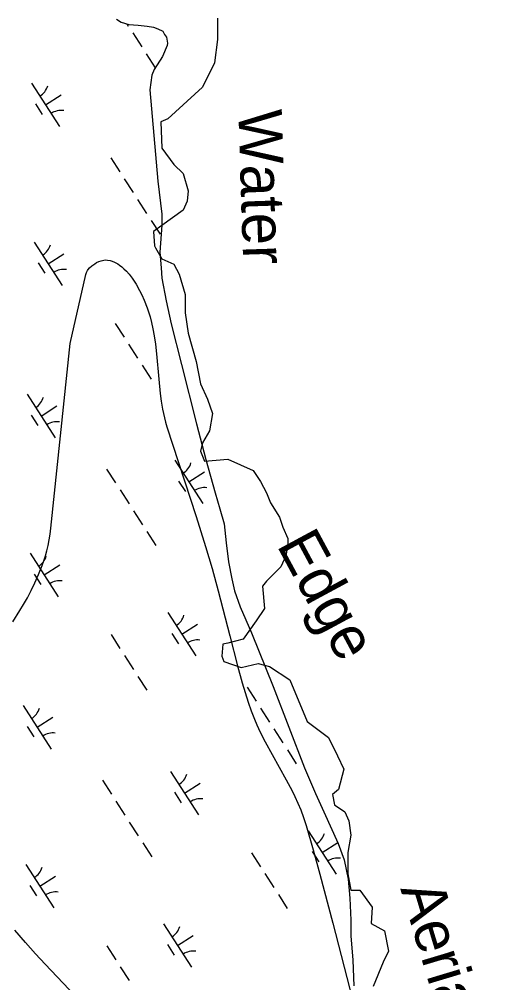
# Model space of a CAD drawing. Extents: x 3937982 to 3958556, y 219448 to 241894.
# Drawn here: x 3947936 to 3948387, y 229125 to 230057 of the extents above; entities that cross this region are included whole.
import ezdxf

# ---------------------------------------------------------------- set-up
doc = ezdxf.new("R2010")
doc.units = 0
for name, color, linetype in [('V-RIVR-EDGE', 7, 'Continuous'), ('V-RIVR-IDEN', 7, 'Continuous'), ('V-SITE-VEGE', 7, 'Continuous'), ('V-WETL-SWMP', 7, 'Continuous')]:
    doc.layers.add(name, color=color, linetype=linetype)

msp = doc.modelspace()

# ---------------------------------------------------------------- linework, layer by layer
at = {"layer": 'V-RIVR-EDGE'}
msp.add_lwpolyline([(3948127.892, 230057.732), (3948127.892, 230037.092), (3948124.944, 230014.485), (3948113.149, 229990.895), (3948079.73, 229960.426), (3948072.85, 229957.477), (3948073.833, 229931.922), (3948085.628, 229916.195), (3948094.474, 229907.349), (3948099.388, 229890.64), (3948098.405, 229880.811), (3948094.474, 229871.965), (3948073.833, 229857.222), (3948065.97, 229851.324), (3948066.953, 229837.564), (3948067.936, 229835.598), (3948073.833, 229824.786), (3948085.628, 229819.872), (3948090.542, 229810.043), (3948096.44, 229790.385), (3948096.44, 229772.693), (3948099.388, 229753.035), (3948107.251, 229725.514), (3948111.183, 229703.89), (3948118.063, 229689.146), (3948122.978, 229675.386), (3948120.029, 229658.677), (3948113.149, 229646.882), (3948111.183, 229639.019), (3948115.115, 229629.19), (3948137.721, 229631.156), (3948162.294, 229620.344), (3948169.174, 229609.532), (3948175.071, 229598.72), (3948179.003, 229588.891), (3948187.849, 229575.13), (3948190.798, 229565.302), (3948195.712, 229554.49), (3948195.712, 229548.592), (3948193.746, 229537.78), (3948188.832, 229526.969), (3948175.071, 229513.208), (3948171.14, 229508.294), (3948173.105, 229486.67), (3948165.242, 229474.875), (3948152.465, 229457.183), (3948137.721, 229453.251), (3948132.807, 229452.268), (3948131.824, 229440.474), (3948133.79, 229435.559), (3948150.499, 229429.662), (3948167.208, 229433.593), (3948178.02, 229430.645), (3948197.678, 229417.867), (3948214.387, 229377.568), (3948235.028, 229361.842), (3948243.874, 229344.15), (3948249.771, 229331.372), (3948244.857, 229311.714), (3948238.959, 229306.8), (3948240.925, 229296.971), (3948250.754, 229290.091), (3948254.686, 229281.245), (3948256.652, 229267.484), (3948253.703, 229250.775), (3948253.703, 229230.134), (3948256.652, 229214.408), (3948265.498, 229214.408), (3948277.292, 229197.698), (3948276.309, 229181.972), (3948289.087, 229175.092), (3948293.019, 229155.434), (3948288.104, 229144.622), (3948278.275, 229121.033)], dxfattribs=at)
at = {"layer": 'V-SITE-VEGE'}
for points in [[(3947951.202, 229511.544), (3947954.778, 229519.604), (3947958.182, 229528.323), (3947959.758, 229532.871), (3947961.247, 229537.602), (3947962.636, 229542.528), (3947963.895, 229547.654), (3947965.008, 229552.991), (3947965.945, 229558.559), (3947966.677, 229564.361), (3947985.369, 229743.168), (3948000.321, 229809.784), (3948000.96, 229811.727), (3948001.951, 229813.583), (3948002.785, 229814.764), (3948004.073, 229816.257), (3948006.058, 229818.092), (3948009.031, 229820.21), (3948010.829, 229821.232), (3948012.91, 229822.215), (3948015.251, 229823.069), (3948017.776, 229823.667), (3948019.013, 229823.806), (3948021.493, 229823.741), (3948024.057, 229823.247), (3948025.802, 229822.7), (3948028.147, 229821.715), (3948031.281, 229819.985), (3948033.056, 229818.801), (3948035.059, 229817.289), (3948037.296, 229815.372), (3948039.757, 229812.962), (3948042.414, 229809.964), (3948045.183, 229806.277), (3948049.047, 229800.275), (3948052.459, 229794.254), (3948054.495, 229790.231), (3948056.932, 229784.857), (3948059.728, 229777.677), (3948061.112, 229773.569), (3948062.519, 229768.869), (3948063.92, 229763.491), (3948065.278, 229757.338), (3948066.556, 229750.303), (3948067.719, 229742.261), (3948068.757, 229733.072), (3948070.862, 229708.629), (3948072.263, 229694.737), (3948073.252, 229687.362), (3948074.58, 229679.525), (3948076.392, 229671.206), (3948077.514, 229666.929), (3948078.827, 229662.53), (3948107.081, 229575.814), (3948116.209, 229546.831), (3948119.425, 229536.095), (3948122.509, 229525.32), (3948128.383, 229503.671), (3948139.563, 229460.188), (3948147.163, 229431.241), (3948151.748, 229414.78), (3948157.331, 229396.071), (3948160.176, 229387.758), (3948163.428, 229379.601), (3948165.795, 229374.239), (3948169.156, 229367.168), (3948173.93, 229357.851), (3948194.291, 229321.071), (3948199.827, 229310.457), (3948202.619, 229304.732), (3948205.435, 229298.568), (3948208.222, 229291.91), (3948210.911, 229284.701), (3948213.407, 229276.867), (3948220.104, 229253.303), (3948226.621, 229229.692), (3948239.235, 229182.356), (3948258.267, 229108.575)], [(3947929.659, 229473.676), (3947936.669, 229484.745), (3947940.231, 229490.719), (3947943.866, 229497.148), (3947947.538, 229504.074), (3947951.202, 229511.544)], [(3948007.966, 229093.315), (3947961.088, 229142.615), (3947951.734, 229152.722), (3947941.902, 229163.627), (3947931.635, 229175.442)]]:
    msp.add_lwpolyline(points, dxfattribs=at)
at = {"layer": 'V-WETL-SWMP'}
for p, q in [((3948030.207, 230056.64), (3948034.43, 230053.886)), ((3948034.43, 230053.886), (3948042.144, 230051.633)), ((3948040.128, 230052.222), (3948041.499, 230050.092)), ((3948042.144, 230051.633), (3948051.009, 230050.79)), ((3948051.009, 230050.79), (3948059.64, 230049.946)), ((3948059.64, 230049.946), (3948065.709, 230049.075)), ((3948065.709, 230049.075), (3948070.153, 230047.488)), ((3948070.153, 230047.488), (3948074.84, 230044.972)), ((3948045.829, 230043.365), (3948054.489, 230029.911)), ((3948074.84, 230044.972), (3948076.502, 230041.959)), ((3948076.502, 230041.959), (3948078.394, 230039.182)), ((3948078.394, 230039.182), (3948079.383, 230033.598)), ((3948078.941, 230031.263), (3948074.386, 230020.729)), ((3948079.383, 230033.598), (3948078.941, 230031.263)), ((3948058.819, 230023.184), (3948067.446, 230009.781)), ((3948074.386, 230020.729), (3948066.357, 230008.062)), ((3948064.081, 230002.679), (3948062.361, 229988.445)), ((3948066.357, 230008.062), (3948064.081, 230002.679)), ((3947947.838, 229994.913), (3947974.9, 229952.87)), ((3947961.369, 229973.892), (3947976.505, 229983.634)), ((3948062.361, 229988.445), (3948070.013, 229900.192)), ((3947951.634, 229974.761), (3947958.129, 229964.671)), ((3948024.539, 229922.628), (3948033.199, 229909.174)), ((3948037.529, 229902.448), (3948046.189, 229888.994)), ((3948070.013, 229900.192), (3948073.834, 229868.068)), ((3948050.519, 229882.267), (3948059.178, 229868.813)), ((3948063.508, 229862.086), (3948072.168, 229848.632)), ((3948073.834, 229868.068), (3948073.94, 229857.581)), ((3948073.94, 229857.581), (3948072.109, 229831.227)), ((3947950.536, 229841.194), (3947977.599, 229799.151)), ((3947964.068, 229820.172), (3947979.203, 229829.915)), ((3948072.109, 229831.227), (3948073.195, 229816.089)), ((3947954.332, 229821.041), (3947960.827, 229810.951)), ((3948073.195, 229816.089), (3948073.762, 229806.073)), ((3948073.762, 229806.073), (3948078.176, 229784.443)), ((3948078.176, 229784.443), (3948083.063, 229762.118)), ((3948028.8, 229762.498), (3948037.46, 229749.044)), ((3948083.063, 229762.118), (3948092.784, 229722.829)), ((3948041.79, 229742.317), (3948050.449, 229728.863)), ((3948054.779, 229722.137), (3948063.439, 229708.683)), ((3948092.784, 229722.829), (3948107.584, 229665.18)), ((3947943.798, 229693.866), (3947970.861, 229651.822)), ((3947957.33, 229672.844), (3947972.465, 229682.586)), ((3947947.594, 229673.713), (3947954.089, 229663.623)), ((3948107.584, 229665.18), (3948116.556, 229630.777)), ((3948086.364, 229630.175), (3948113.427, 229588.132)), ((3948116.556, 229630.777), (3948125.506, 229598.472)), ((3948020.499, 229621.581), (3948029.159, 229608.127)), ((3948099.895, 229609.154), (3948115.031, 229618.896)), ((3948090.16, 229610.023), (3948096.655, 229599.933)), ((3948033.489, 229601.4), (3948042.149, 229587.946)), ((3948125.506, 229598.472), (3948130.089, 229583.137)), ((3948046.479, 229581.219), (3948055.139, 229567.765)), ((3948130.089, 229583.137), (3948134.199, 229568.495)), ((3948134.199, 229568.495), (3948136.25, 229550.104)), ((3948059.469, 229561.038), (3948068.129, 229547.584)), ((3948136.25, 229550.104), (3948138.534, 229531.715)), ((3947946.497, 229540.146), (3947973.559, 229498.103)), ((3947960.028, 229519.124), (3947975.164, 229528.867)), ((3948138.534, 229531.715), (3948141.495, 229515.431)), ((3947950.293, 229519.994), (3947956.788, 229509.903)), ((3948141.495, 229515.431), (3948144.177, 229503.805)), ((3948144.177, 229503.805), (3948149.692, 229488.479)), ((3948149.692, 229488.479), (3948160.669, 229463.186)), ((3948079.626, 229482.847), (3948106.689, 229440.804)), ((3948093.157, 229461.826), (3948108.293, 229471.568)), ((3948024.76, 229461.45), (3948033.42, 229447.996)), ((3948083.422, 229462.695), (3948089.917, 229452.605)), ((3948160.669, 229463.186), (3948181.472, 229411.191)), ((3948037.75, 229441.27), (3948046.41, 229427.816)), ((3948050.74, 229421.089), (3948059.4, 229407.635)), ((3948156.327, 229410.562), (3948164.987, 229397.108)), ((3948181.472, 229411.191), (3948211.865, 229332.724)), ((3947939.759, 229392.818), (3947966.821, 229350.775)), ((3948169.317, 229390.382), (3948177.977, 229376.928)), ((3947953.29, 229371.796), (3947968.426, 229381.539)), ((3947943.555, 229372.665), (3947950.05, 229362.575)), ((3948182.307, 229370.201), (3948190.967, 229356.747)), ((3948195.297, 229350.02), (3948203.957, 229336.566)), ((3948211.865, 229332.724), (3948222.371, 229307.893)), ((3948016.46, 229320.533), (3948025.12, 229307.079)), ((3948082.325, 229329.128), (3948109.387, 229287.084)), ((3948095.856, 229308.106), (3948110.992, 229317.849)), ((3948086.121, 229308.975), (3948092.616, 229298.885)), ((3948222.371, 229307.893), (3948230.476, 229290.029)), ((3948029.45, 229300.352), (3948038.11, 229286.898)), ((3948230.476, 229290.029), (3948244.537, 229259.407)), ((3948042.44, 229280.171), (3948051.1, 229266.717)), ((3948215.454, 229271.829), (3948242.516, 229229.786)), ((3948055.43, 229259.991), (3948064.09, 229246.537)), ((3948228.985, 229250.808), (3948244.037, 229260.496)), ((3948244.537, 229259.407), (3948250.29, 229243.617)), ((3948160.588, 229250.432), (3948169.248, 229236.978)), ((3948219.25, 229251.677), (3948225.745, 229241.586)), ((3947942.458, 229239.098), (3947969.52, 229197.055)), ((3948250.29, 229243.617), (3948254.21, 229224.779)), ((3947955.989, 229218.077), (3947971.124, 229227.819)), ((3948173.578, 229230.251), (3948182.238, 229216.797)), ((3947946.254, 229218.946), (3947952.749, 229208.855)), ((3948254.21, 229224.779), (3948255.559, 229206.614)), ((3948186.568, 229210.071), (3948195.228, 229196.617)), ((3948255.559, 229206.614), (3948256.706, 229185.416)), ((3948075.587, 229181.8), (3948102.649, 229139.756)), ((3948256.706, 229185.416), (3948256.628, 229170.034)), ((3948079.383, 229161.647), (3948085.878, 229151.557)), ((3948089.118, 229160.778), (3948104.254, 229170.52)), ((3948256.628, 229170.034), (3948258.731, 229146.516)), ((3948020.721, 229160.403), (3948029.381, 229146.949)), ((3948258.731, 229146.516), (3948259.682, 229121.588)), ((3948033.711, 229140.222), (3948042.371, 229126.768))]:
    msp.add_line(p, q, dxfattribs=at)
for centre, start, end in [((3947946.619, 229997.246), 301.99668, 343.540338), ((3947976.519, 229950.794), 81.996677, 123.540335), ((3947949.317, 229843.527), 301.99668, 343.540338), ((3947979.217, 229797.075), 81.996677, 123.540335), ((3947942.579, 229696.198), 301.99668, 343.540338), ((3947972.479, 229649.747), 81.996677, 123.540335), ((3948085.145, 229632.508), 301.99668, 343.540338), ((3948115.045, 229586.056), 81.996677, 123.540335), ((3947945.278, 229542.479), 301.99668, 343.540338), ((3947975.178, 229496.027), 81.996677, 123.540335), ((3948078.407, 229485.18), 301.99668, 343.540338), ((3948108.307, 229438.728), 81.996677, 123.540335), ((3947938.54, 229395.151), 301.99668, 343.540338), ((3947968.44, 229348.699), 81.996677, 123.540335), ((3948081.106, 229331.46), 301.99668, 343.540338), ((3948111.006, 229285.009), 81.996677, 123.540335), ((3948214.235, 229274.162), 301.99668, 343.540338), ((3948244.135, 229227.71), 81.996677, 123.540335), ((3947941.238, 229241.431), 301.99668, 343.540338), ((3947971.138, 229194.979), 81.996677, 123.540335), ((3948074.368, 229184.132), 301.99668, 343.540338), ((3948104.268, 229137.681), 81.996677, 123.540335)]:
    msp.add_arc(centre, 17.623, start, end, dxfattribs=at)

# ---------------------------------------------------------------- texts
at = {"layer": 'V-RIVR-IDEN'}
for s, rotation, p in [('Water', 271.831635, (3948147.873, 229968.764)), ('Edge', 298.355344, (3948184.466, 229548.176)), ('Aerial', 286.777012, (3948304.423, 229215.757))]:
    msp.add_text(s, height=41.9999, rotation=rotation, dxfattribs=at).set_placement(p)

doc.saveas('drawing.dxf')
